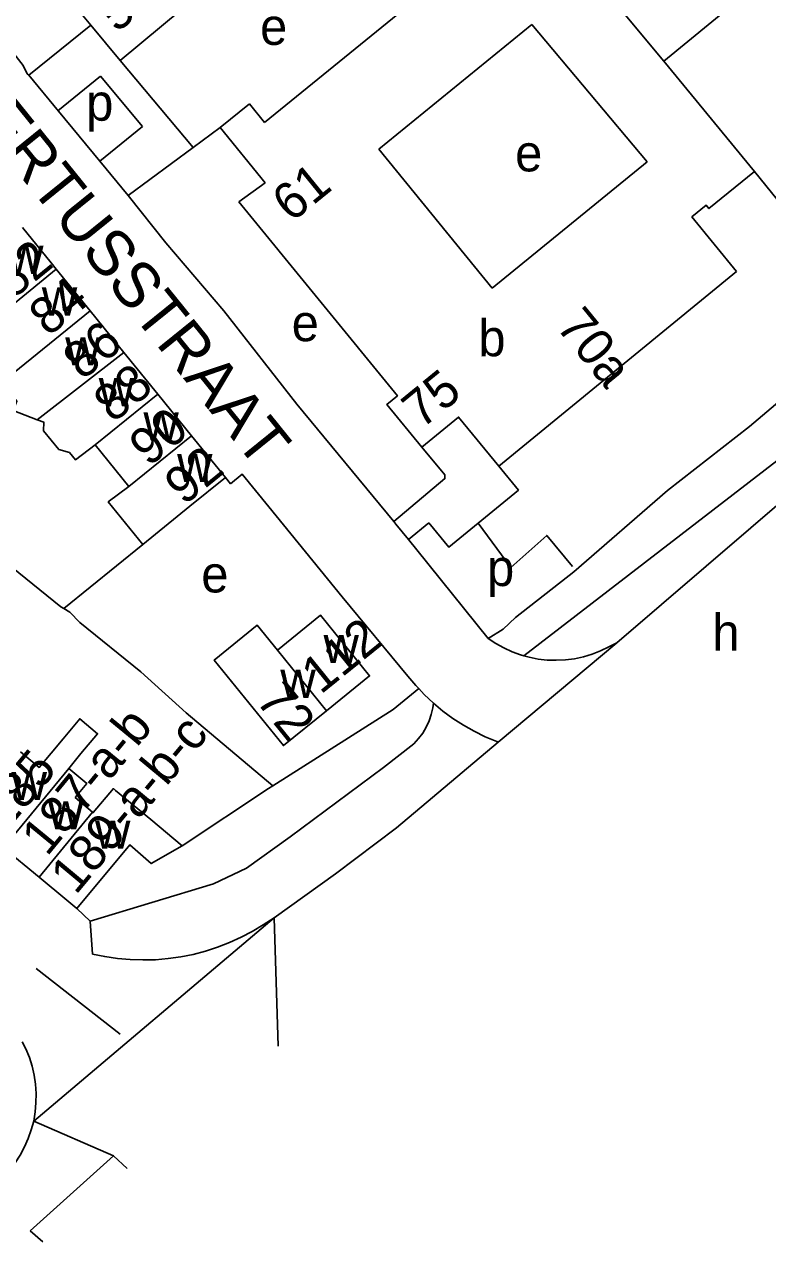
# Model space of a CAD drawing. Extents: x 161141 to 163125, y 381621 to 383200.
# Drawn here: x 162497.1 to 162578.3, y 381807.4 to 381940.5 of the extents above; entities that cross this region are included whole.
import ezdxf

# ---------------------------------------------------------------- set-up
doc = ezdxf.new("R2010")
doc.units = 0
for name, color, linetype in [('BLT_Basislijn', 7, 'Continuous'), ('BLT_Bebouwing', 7, 'Continuous'), ('BLT_Centroide', 7, 'Continuous'), ('BLT_Huisnummer', 7, 'Continuous'), ('BLT_Huisnummer_ tussenligend', 7, 'Continuous'), ('BLT_Huisnummer_reeks', 7, 'Continuous'), ('BLT_Onderverdeling_panden', 7, 'Continuous'), ('BLT_Straatnaam', 7, 'Continuous'), ('BLT_Vlakafsluiter', 7, 'Continuous')]:
    doc.layers.add(name, color=color, linetype=linetype)

msp = doc.modelspace()

# ---------------------------------------------------------------- linework, layer by layer
at = {"layer": 'BLT_Basislijn'}
for p, q in [((162504.33, 381940.42), (162497.57, 381934.92)), ((162507.56, 381936.54), (162515.54, 381927.04)), ((162505.38, 381934.82), (162500.74, 381931.05)), ((162505.38, 381934.82), (162509.98, 381929.31)), ((162509.98, 381929.31), (162505.32, 381925.54)), ((162515.54, 381927.04), (162518.48, 381929.21)), ((162508.41, 381921.77), (162515.54, 381927.04)), ((162561.84, 381872.89), (162584.56, 381892.43)), ((162519.59, 381890.28), (162519.04, 381890.97)), ((162523.78, 381887.75), (162531.81, 381877.91)), ((162541.28, 381886.01), (162539.04, 381884.2)), ((162501.39, 381876.64), (162510.03, 381883.65)), ((162538.97, 381869.26), (162531.81, 381877.91)), ((162524.22, 381857.26), (162523.75, 381856.97)), ((162524.36, 381842.82), (162531.09, 381847.63)), ((162504.26, 381842.48), (162502.81, 381843.85)), ((162504.26, 381842.48), (162504.51, 381838.88)), ((162498.38, 381837.31), (162507.55, 381830.11)), ((162499.09, 381807.44), (162497.72, 381808.64))]:
    msp.add_line(p, q, dxfattribs=at)
for points in [[(162497.57, 381934.92), (162497.4, 381935.1), (162496.93, 381936), (162493.3, 381940.62), (162491.66, 381942.59)], [(162500.79, 381931), (162497.57, 381934.92)], [(162505.32, 381925.54), (162500.79, 381931)], [(162508.41, 381921.77), (162505.32, 381925.54)], [(162508.41, 381921.77), (162512.52, 381916.63), (162518.87, 381909.19), (162526.86, 381898.99), (162537.45, 381886.14)], [(162583.67, 381902.76), (162576.33, 381896.53), (162567.38, 381889.55), (162557.11, 381880.66), (162550.74, 381875.65), (162549.41, 381874.38), (162547.78, 381873.38)], [(162473.72, 381899.48), (162478.6, 381895.42), (162483.73, 381891.53), (162490.91, 381885.04), (162501.06, 381876.83), (162501.39, 381876.64)], [(162551.66, 381871.48), (162583.75, 381896.22), (162584.96, 381897.21)], [(162540.51, 381894.28), (162543.04, 381891.25), (162543.04, 381890.84), (162537.45, 381886.14)], [(162548.92, 381892.21), (162551.07, 381889.58), (162546.67, 381885.98)], [(162519.59, 381890.28), (162520.88, 381891.32), (162523.78, 381887.75)], [(162537.45, 381886.14), (162537.68, 381885.85), (162539.04, 381884.2)], [(162541.28, 381886.01), (162543.45, 381883.35), (162546.67, 381885.98)], [(162546.67, 381885.98), (162550.25, 381881.11), (162554.16, 381884.64), (162556.97, 381881.24)], [(162547.78, 381873.38), (162539.97, 381883.06), (162539.04, 381884.2)], [(162501.39, 381876.64), (162502.05, 381876.25), (162503.15, 381875.13), (162509.82, 381869.71), (162514.76, 381865.25), (162524.22, 381857.26)], [(162547.78, 381873.38), (162548.6, 381872.83), (162549.46, 381872.34), (162550.37, 381871.92), (162551.3, 381871.58), (162551.66, 381871.48)], [(162551.66, 381871.48), (162552.26, 381871.31), (162553.23, 381871.12), (162554.22, 381871.01), (162555.21, 381870.98), (162556.21, 381871.03), (162557.19, 381871.16), (162558.17, 381871.37), (162559.12, 381871.65), (162560.04, 381872.01), (162560.94, 381872.45), (162561.84, 381872.89)], [(162538.97, 381869.26), (162539.85, 381868.22), (162540.17, 381867.89)], [(162540.17, 381867.89), (162537.39, 381865.61), (162524.22, 381857.26)], [(162540.17, 381867.89), (162540.78, 381867.24), (162541.78, 381866.3)], [(162539.65, 381861.87), (162540.16, 381862.42), (162540.61, 381863.02), (162541, 381863.66), (162541.31, 381864.35), (162541.55, 381865.06), (162541.71, 381865.79), (162541.78, 381866.3)], [(162541.78, 381866.3), (162542.82, 381865.44), (162543.91, 381864.64), (162545.05, 381863.9), (162546.24, 381863.23), (162547.45, 381862.63), (162548.71, 381862.1), (162548.84, 381862.05)], [(162504.26, 381842.48), (162517.76, 381846.54), (162521.36, 381848.26), (162526.13, 381851.68), (162536.31, 381859.26), (162539.65, 381861.87)], [(162548.84, 381862.05), (162537.76, 381852.67), (162531.09, 381847.63)], [(162523.75, 381856.97), (162514.33, 381850.71)], [(162504.51, 381838.88), (162505.87, 381838.6), (162507.25, 381838.39), (162508.63, 381838.27), (162510.02, 381838.23), (162511.41, 381838.26), (162512.8, 381838.38), (162514.17, 381838.57), (162515.54, 381838.84), (162516.88, 381839.2), (162518.2, 381839.62), (162519.5, 381840.13), (162520.76, 381840.71), (162521.99, 381841.35), (162523.18, 381842.07), (162524.36, 381842.82)], [(162498.1, 381820.61), (162498.25, 381821.63), (162498.34, 381822.63), (162498.36, 381823.64), (162498.29, 381824.64), (162498.14, 381825.64), (162497.92, 381826.61), (162497.62, 381827.57), (162497.24, 381828.51), (162496.85, 381829.3)], [(162493.29, 381813.19), (162494.07, 381813.82), (162494.8, 381814.52), (162495.47, 381815.27), (162496.08, 381816.07), (162496.62, 381816.91), (162497.1, 381817.8), (162497.5, 381818.72), (162497.83, 381819.67), (162498.1, 381820.61)], [(162497.72, 381808.64), (162506.81, 381816.83)], [(162506.81, 381816.83), (162508.32, 381815.42)]]:
    msp.add_lwpolyline(points, dxfattribs=at)
at = {"layer": 'BLT_Bebouwing'}
for p, q in [((162559.25, 381945.74), (162566.98, 381936.48)), ((162542.06, 381945.01), (162523.33, 381929.78)), ((162552.55, 381940.48), (162535.82, 381926.86)), ((162552.55, 381940.48), (162565.14, 381925.47)), ((162521.68, 381931.81), (162518.48, 381929.21)), ((162521.68, 381931.81), (162523.33, 381929.78)), ((162523.39, 381923.18), (162518.48, 381929.21)), ((162535.82, 381926.86), (162548.19, 381911.66)), ((162565.14, 381925.47), (162548.19, 381911.66)), ((162579.36, 381921.35), (162576.86, 381924.41)), ((162520.5, 381921.1), (162523.39, 381923.18)), ((162504.26, 381909.17), (162500.56, 381913.72)), ((162548.92, 381892.21), (162574.91, 381913.48)), ((162507.95, 381904.62), (162504.26, 381909.17)), ((162511.65, 381900.07), (162507.95, 381904.62)), ((162515.34, 381895.53), (162511.65, 381900.07)), ((162519.04, 381890.97), (162515.34, 381895.53)), ((162504.82, 381894.53), (162508.51, 381889.98)), ((162498.69, 381847.29), (162494.79, 381850.49))]:
    msp.add_line(p, q, dxfattribs=at)
for points in [[(162504.33, 381940.42), (162498.86, 381947), (162526.54, 381970.04)], [(162534.66, 381959.09), (162507.56, 381936.54)], [(162566.98, 381936.48), (162584.53, 381950.9), (162593.53, 381939.54), (162596.7, 381935.67)], [(162507.56, 381936.54), (162504.33, 381940.42)], [(162574.91, 381913.48), (162570.04, 381919.45), (162571.6, 381920.72), (162571.89, 381920.36), (162576.86, 381924.41)], [(162520.5, 381921.1), (162537.85, 381899.89), (162536.69, 381898.95), (162540.51, 381894.28)], [(162500.56, 381913.72), (162500, 381914.41), (162496.86, 381918.27)], [(162498.48, 381897.28), (162495.87, 381898.27), (162496.26, 381899.29), (162494.6, 381901.33)], [(162498.48, 381897.28), (162499.21, 381897.01), (162499.18, 381896.08), (162500.85, 381894.02), (162502, 381893.71), (162502.65, 381892.91), (162504.82, 381894.53)], [(162540.51, 381894.28), (162544.53, 381897.57), (162548.92, 381892.21)], [(162510.03, 381883.65), (162515.16, 381887.82), (162519.04, 381890.97)], [(162508.51, 381889.98), (162506.25, 381888.3), (162510.03, 381883.65)], [(162524.73, 381872.1), (162522.53, 381874.81), (162517.82, 381871), (162525.38, 381861.66), (162530.09, 381865.47)], [(162530.09, 381865.47), (162534.8, 381869.28), (162529.44, 381875.91), (162524.73, 381872.1)], [(162501.92, 381859.16), (162503.26, 381860.78), (162505.08, 381862.95), (162503.12, 381864.59), (162501.3, 381862.41), (162498.7, 381859.28), (162496.65, 381860.99)], [(162502.62, 381855.98), (162503.89, 381857.51), (162501.92, 381859.16)], [(162514.33, 381850.71), (162510.9, 381853.57), (162507.05, 381856.77), (162506.81, 381856.97), (162504.61, 381854.33), (162504.53, 381854.4)], [(162504.53, 381854.4), (162502.62, 381855.98)], [(162502.81, 381843.85), (162508.61, 381850.83), (162510.95, 381848.76), (162514.33, 381850.71)], [(162502.81, 381843.85), (162501.72, 381844.76), (162498.69, 381847.29)]]:
    msp.add_lwpolyline(points, dxfattribs=at)
at = {"layer": 'BLT_Onderverdeling_panden'}
for p, q in [((162566.98, 381936.48), (162576.86, 381924.41)), ((162493.73, 381908.17), (162500.56, 381913.72)), ((162494.6, 381901.33), (162504.26, 381909.17)), ((162498.48, 381897.28), (162507.95, 381904.62)), ((162504.82, 381894.53), (162511.65, 381900.07)), ((162508.51, 381889.98), (162515.34, 381895.53)), ((162524.73, 381872.1), (162530.09, 381865.47)), ((162501.92, 381859.16), (162494.79, 381850.49)), ((162498.69, 381847.29), (162504.53, 381854.4))]:
    msp.add_line(p, q, dxfattribs=at)
at = {"layer": 'BLT_Vlakafsluiter'}
for p, q in [((162561.84, 381872.89), (162548.84, 381862.05)), ((162524.36, 381842.82), (162498.1, 381820.61)), ((162524.8, 381828.8), (162524.36, 381842.82)), ((162506.81, 381816.83), (162498.1, 381820.61))]:
    msp.add_line(p, q, dxfattribs=at)

# ---------------------------------------------------------------- texts
at = {"layer": 'BLT_Centroide'}
for s, p in [('e', (162522.84, 381938.25)), ('p', (162503.83, 381929.96)), ('e', (162550.71, 381924.42)), ('w', (162495.3, 381913.22)), ('w', (162498.99, 381908.66)), ('e', (162526.29, 381905.86)), ('b', (162546.69, 381904.22)), ('w', (162501.54, 381903.22)), ('w', (162505.21, 381898.75)), ('w', (162510.09, 381895.03)), ('w', (162513.77, 381890.47)), ('e', (162516.41, 381878.4)), ('p', (162547.64, 381879.1)), ('h', (162572.27, 381872.04)), ('w', (162529.77, 381870.69)), ('w', (162525.05, 381866.88)), ('w', (162495.69, 381855.72)), ('w', (162499.67, 381852.5)), ('w', (162504.8, 381850.39))]:
    msp.add_text(s, height=4, dxfattribs=at).set_placement(p)
at = {"layer": 'BLT_Huisnummer'}
for s, rotation, p in [('84', 39.0932, (162499.69, 381906.29)), ('88', 39.0932, (162506.76, 381896.84)), ('92', 39.0931, (162514.51, 381887.83)), ('112', 38.9677, (162529.45, 381867.18)), ('72', 308.9724, (162522.27, 381866.55)), ('185', 50.2151, (162495.06, 381852.18))]:
    msp.add_text(s, height=4, rotation=rotation, dxfattribs=at).set_placement(p)
at = {"layer": 'BLT_Huisnummer_ tussenligend'}
for s, rotation, p in [('82', 39.0942, (162495.82, 381910.37)), ('86', 39.0932, (162503.41, 381901.51)), ('90', 39.0932, (162510.65, 381892.05))]:
    msp.add_text(s, height=4, rotation=rotation, dxfattribs=at).set_placement(p)
at = {"layer": 'BLT_Huisnummer_reeks'}
for s, rotation, p in [('59-a t/m d', 39.6428, (162507.18, 381939.49)), ('61', 39.1198, (162526.27, 381918.76)), ('70a', 309.158, (162555.08, 381907.43)), ('75', 39.285, (162540.48, 381896.19)), ('187-a-b', 50.5971, (162499.55, 381849.45)), ('189-a-b-c', 50.2194, (162502.69, 381845.25))]:
    msp.add_text(s, height=4, rotation=rotation, dxfattribs=at).set_placement(p)
at = {"layer": 'BLT_Straatnaam'}
msp.add_text('ST HUBERTUSSTRAAT', height=5, rotation=308.8959, dxfattribs=at).set_placement((162476.37, 381948.96))

doc.saveas('drawing.dxf')
